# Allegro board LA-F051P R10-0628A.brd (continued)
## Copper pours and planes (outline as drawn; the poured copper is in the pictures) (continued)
SPK_L+_C on BOTTOM (solid shape): 26.65,17.36 26.65,16.6 26.52,16.47 24.49,16.47 23.98,15.96 22.45,15.96 22.2,16.21 22.2,16.85 22.58,17.23 22.96,17.23 23.22,17.48 26.52,17.48
SPK_L-_C on TOP (solid shape): 26.14,20.28 26.14,17.74 25.63,17.23 25.63,15.45 24.49,14.31 22.2,14.31 22.07,14.44 22.07,15.45 22.2,15.58 23.98,15.58 24.49,16.09 24.49,17.48 25.25,18.25 25.25,19.67 25.1,19.67 24.99,19.77 24.99,20.28 25.12,20.41 26.01,20.41
SPK_L-_C on BOTTOM (solid shape): 26.77,15.96 26.77,15.58 26.65,15.45 25.25,15.45 24.61,14.82 24.61,13.93 24.36,13.67 23.47,13.67 23.22,13.93 23.22,14.69 24.74,16.21 26.52,16.21
SPK_OUT_L+ on TOP (solid shape): 27.57,27.02 27.57,25.36 27.53,25.32 27.53,24.99 27.05,24.5 26.83,24.5 26.7,24.62 26.7,24.82 27.33,25.45 27.33,27.02 27.39,27.07 27.52,27.07
SPK_OUT_L+ on TOP (solid shape): 23.35,21.8 23.54,21.74 23.72,21.8 24.61,21.8 24.74,21.68 24.74,20.66 24.61,20.53 24.29,20.53 24.23,20.53 24.23,20.54 23.33,20.54 23.32,20.55 23.28,20.64 23.22,20.72 23.22,21.68 23.34,21.8
SPK_OUT_L+ on IN1 (solid shape): 28.8,25.13 28.8,23.38 27.44,22.01 27.41,22.02 27.01,21.95 26.93,21.55 26.95,21.52 25.71,20.28 24.11,20.28 23.98,20.41 23.98,21.55 24.11,21.68 25.12,21.68 27.15,23.71 27.15,24.39 26.82,24.72 26.82,25 27.07,25.25 27.15,25.31 27.21,25.39 27.23,25.41 28.52,25.41
SPK_OUT_L- on TOP (solid shape): 27.97,27.03 27.97,25.3 28.04,25.23 28.04,25.1 28.42,24.72 28.42,24.22 27.79,23.58 27.79,22.31 27.47,21.99 27.43,22.01 27.01,21.95 26.95,21.52 26.97,21.49 26.02,20.54 25.11,20.54 24.99,20.66 24.99,21.55 26.39,22.95 26.39,23.58 27.66,24.85 27.66,24.97 27.67,24.98 27.71,25.12 27.7,25.27 27.69,25.28 27.69,25.3 27.74,25.35 27.74,27.03 27.79,27.08 27.93,27.08
SPK_OUT_R+ on TOP (solid shape): 28.83,26.99 28.83,26 28.82,25.99 28.82,25.71 28.83,25.68 28.93,25.46 29.15,25.36 29.17,25.36 29.62,24.91 29.66,24.91 29.67,24.9 30.35,24.9 30.59,24.66 30.59,22.77 30.5,22.67 30.5,21.76 30.59,21.66 30.59,21.15 29.37,21.15 29.31,21.21 29.31,23.07 29.57,23.33 29.57,24.52 28.53,25.55 28.53,27 28.61,27.08 28.74,27.08
SPK_OUT_R- on TOP (solid shape): 28.37,27.01 28.37,25.53 29.44,24.47 29.44,23.45 29.06,23.07 29.06,20.66 28.93,20.53 28.17,20.53 28.05,20.65 28.05,21.42 28.04,21.42 28.04,23.58 28.55,24.09 28.55,24.78 28.17,25.16 28.17,25.28 28.14,25.31 28.14,27.01 28.2,27.07 28.31,27.07
SPK_R+_C on TOP (solid shape): 30.69,20.8 30.69,19.98 30.96,19.7 30.96,16.85 30.62,16.51 30.52,16.49 30.45,16.57 29.85,16.77 30.05,16.17 30.13,16.1 30.11,15.99 30.07,15.96 30.07,14.94 29.98,14.8 29.98,14.62 29.98,14.6 29.82,14.44 28.42,14.44 28.17,14.69 28.17,16.34 30.07,18.25 30.07,18.47 30.27,18.75 30.17,19.07 30.07,19.17 30.07,19.26 29.95,19.39 29.95,20.15 29.73,20.37 29.73,20.39 29.72,20.47 29.7,20.54 29.69,20.55 29.69,20.79 29.82,20.91 30.58,20.91
SPK_R+_C on BOTTOM (solid shape): 29.72,14.92 29.72,13.95 29.08,13.32 25.35,13.32 24.99,13.67 24.99,14.13 25.2,14.33 28.19,14.33 28.85,14.99 29.64,14.99
SPK_R-_C on TOP (solid shape): 27.92,21.42 27.92,19.26 27.28,18.63 27.28,18.27 27.28,18.25 27.28,17.74 27.28,17.72 27.28,16.98 27.66,16.6 27.66,14.69 27.41,14.44 26.39,14.44 26.14,14.69 26.14,17.36 26.26,17.48 26.26,17.69 26.26,17.69 26.26,20.08 26.71,20.08 26.71,20.02 26.72,19.97 26.73,19.92 26.76,19.87 26.79,19.83 26.82,19.79 26.86,19.75 26.91,19.73 26.96,19.71 27.01,19.7 27.06,19.69 27.12,19.7 27.17,19.71 27.22,19.73 27.27,19.75 27.31,19.79 27.34,19.83 27.37,19.87 27.4,19.92 27.41,19.97 27.42,20.02 27.42,20.08 27.41,20.13 27.4,20.18 27.37,20.23 27.34,20.27 27.31,20.31 27.27,20.34 27.22,20.37 27.17,20.39 27.12,20.4 27.06,20.41 27.01,20.4 26.96,20.39 26.91,20.37 26.86,20.34 26.82,20.31 26.79,20.27 26.76,20.23 26.73,20.18 26.72,20.13 26.71,20.08 26.26,20.08 26.26,20.33 26.26,20.33 26.26,20.53 27.11,21.38 27.16,21.36 27.21,21.35 27.27,21.34 27.32,21.35 27.37,21.36 27.42,21.38 27.47,21.41 27.51,21.44 27.54,21.48 27.57,21.52 27.58,21.55 27.79,21.55
SPK_R-_C on BOTTOM (solid shape): 27.86,14.92 27.86,14.66 27.71,14.51 25.17,14.51 24.99,14.69 24.99,14.94 25.2,15.15 27.64,15.15
TBT_SVR_IND on TOP (solid shape): 38.9,56.16 38.9,56.14 38.91,56.07 38.94,56.01 38.95,55.99 38.95,55.97 39.05,55.86 39.17,55.86 39.2,55.83 39.2,55.66 39.18,55.59 39.11,55.56 38.91,55.47 38.79,55.28 38.57,55.05 38.57,54.17 38.1,53.71 35.32,53.71 35.14,53.88 35.14,54.21 35.18,54.25 36.49,54.25 36.81,54.57 37.95,54.57 38.2,54.82 38.2,55.27 38.21,55.28 38.21,55.41 38.23,55.42 38.33,55.47 38.39,55.57 38.4,55.59 38.41,55.6 38.41,56.04 38.42,56.08 38.64,56.3 38.76,56.3
TBT_SVR_IND on TOP: 34.77,51.11 34.98,51.32 36.09,51.32 36.22,51.44 36.65,51.44 36.81,51.29 36.81,49.78 36.55,49.53 36.55,48.14 36.22,47.81 35.1,47.81 34.77,48.14
TBT_SVR_IND on IN1: 36.64,49.78 35.43,49.78 35.2,50.01 35.2,54.09 35.8,54.68 37.82,54.68 38.1,54.4 38.1,53.13 36.78,51.81 36.78,49.92
TBT_VBUS on TOP (solid shape): 18.87,56.51 18.87,55.42 19.09,55.2 20.39,55.2 20.8,54.79 20.8,53.43 20.68,53.3 17.88,53.3 17.76,53.43 17.76,54.64 17.76,56.15 18.14,56.54 18.15,56.54 18.21,56.6 18.78,56.6
TBT_VBUS on BOTTOM (solid shape): 20.36,58.37 20.36,54.55 20.22,54.42 18.21,54.42 17.71,54.92 17.71,56.06 18.75,57.1 18.75,58.3 19,58.56 20.17,58.56
TBT_VBUS on BOTTOM: 45.13,76.03 46.2,76.03 46.33,75.9 46.32,75.79 46.33,75.71 46.33,75.58 46.52,75.4 48.49,75.4 48.62,75.27 48.62,74.96 48.62,74.43 48.51,74.33 48.24,74.33 47.78,73.87 45.65,73.87 44.69,74.83 44.68,74.83 44.1,75.41 44.1,75.88 44.25,76.03
TBT_VBUS on VCC: 8.84,54.44 5.35,57.94 5.71,58.04 5.87,58.39 5.87,59.19 5.56,59.62 5.06,59.47 5.06,62.11 5.56,61.96 5.86,62.39 5.86,63.19 5.56,63.62 5.06,63.46 5.06,66.64 7.12,67.56 8.1,68.4 8.47,69.64 8.47,70.12 8.98,71.34 10.2,71.85 14.5,71.85 16.11,72.51 16.77,74.12 16.77,79.23 44,79.23 45.15,79.66 45.75,80.73 47.73,80.73 47.73,70.68 44.7,67.65 39.6,67.65 37.57,69.68 31.11,69.68 30.76,69.33 30.76,67.65 24,67.65 21.57,65.21 21.57,55.44 20.57,54.44 ; 4 cut-outs
TBT_VBUS_L on TOP (solid shape): 22.26,59.92 22.26,59.91 22.33,59.79 22.44,59.73 22.45,59.72 22.59,59.59 22.59,59.38 22.28,59.06 22.27,59.06 22.21,59.03 22.18,59 21.82,58.64 21.82,58.63 21.33,58.15 21.18,58.15 21.16,58.13 20.86,58.13 20.79,58.06 20.77,58.06 20.77,58.04 20.73,58 20.73,55.63 20.55,55.46 19.16,55.46 19.09,55.53 19.09,56.4 19.53,56.84 19.53,57.73 20.54,58.74 20.62,58.74 20.63,58.75 20.94,58.8 21.1,59.07 21.1,59.09 21.26,59.25 21.26,59.33 21.29,59.36 21.29,59.45 21.51,59.67 21.69,59.67 21.87,59.85 21.87,60.03 21.95,60.11 22.07,60.11
N52893865 on TOP (solid shape): 174.1,19.47 174.1,18.52 174.47,18.14 174.47,17.61 174.22,17.36 174.04,17.36 173.97,17.39 173.94,17.46 173.79,17.78 173.43,17.81 173.4,17.79 173.2,17.99 172.06,17.99 172,18.06 172,18.7 172.17,18.88 172.7,18.88 173.36,19.54 174.02,19.54
N52893895 on TOP (solid shape): 170.6,18.86 170.6,18.06 170.54,17.99 169.77,17.99 169.65,18.12 168.5,18.12 168.38,18.23 168.38,18.86 168.53,19.01 170.46,19.01
N52922903 on TOP (solid shape): 178.98,31.77 178.98,30.73 178.51,30.26 178.51,29.79 178.23,29.5 178.23,28.66 177.27,28.66 177.14,28.79 177.14,30.99 177.68,31.53 177.93,31.53 178.24,31.84 178.92,31.84
N52922958 on TOP (solid shape): 181.08,31.81 181.08,30.39 181.26,30.2 181.42,30.2 181.53,30.18 181.64,30.2 182.04,30.2 182.04,30.2 182.08,30.16 182.08,29.4 182.03,29.35 180.52,29.35 180.37,29.5 180.37,31.81 180.44,31.89 181,31.89
N52925836 on TOP (solid shape): 50.27,21.57 50.27,20.91 50.19,20.84 48.79,20.84 48.59,21.04 48.3,21.04 48.22,21.12 48.22,22.11 48.23,22.11 48.23,22.3 48.26,22.34 49.5,22.34
N52925896 on TOP (solid shape): 50.29,19.36 50.29,18.75 50.14,18.6 50.14,18.41 50.07,18.36 50.02,18.3 49.96,18.26 49.89,18.28 49.36,17.91 49.97,17.73 50.04,17.76 50.12,17.73 50.14,17.71 50.14,17.23 49.51,16.6 48.79,16.6 47.93,17.46 47.93,19.03 48.08,19.19 48.7,19.19 49.04,19.52 50.14,19.52
N52930519 on TOP (solid shape): 40.36,44.15 40.36,42.25 40.23,42.12 39.22,42.12 38.31,43.03 38.31,43.07 38.27,43.07 38.2,43.14 37.69,43.14 37.57,43.27 37.57,43.9 37.69,44.03 38.58,44.03 38.84,44.28 40.23,44.28
N52930575 on TOP (solid shape): 36.42,45.42 36.42,44.66 36.25,44.48 36.25,43.21 36.17,43.14 35.41,43.14 35.15,43.39 35.15,44.1 35.15,44.15 35.16,44.16 35.18,44.28 35.16,44.39 35.15,44.4 35.15,44.46 34.9,44.72 34.9,45.42 35.03,45.55 36.3,45.55
N52934489 on TOP (solid shape): 28.74,41.99 28.95,41.92 29.17,42 29.44,42 30.01,41.42 30.18,41.42 30.23,41.41 30.28,41.41 31.37,41.41 31.37,41.42 31.6,41.42 31.79,41.23 32.36,41.23 32.49,41.11 32.49,40.6 32.36,40.47 30.25,40.47 30.23,40.5 30.23,40.55 29.97,40.8 29.95,40.83 28.52,40.83 28.42,40.93 28.42,41.74 28.68,42 28.72,42
N52934545 on TOP (solid shape): 34.77,41.11 34.77,39.2 34.65,39.07 33.88,39.07 33.76,39.2 33.76,41.11 33.88,41.23 34.65,41.23
N56704068 on BOTTOM (solid shape): 35.15,77.56 34.65,77.05 34.65,76.54 34.52,76.41 34.27,76.41 33.88,76.79 33.88,79.08 34.01,79.21 35.15,79.21
N56715138 on BOTTOM (solid shape): 50.78,80.69 50.78,78.45 50.69,78.36 48.57,78.36 48.49,78.44 48.11,78.44 47.98,78.57 47.98,80.35 48.4,80.77 50.7,80.77
N56728350 on BOTTOM (solid shape): 55.79,55.14 55.79,54.82 55.54,54.57 55.54,53.81 55.41,53.68 55.11,53.68 54.84,53.4 54.84,53.35 54.84,52.03 54.65,51.83 54.63,51.83 54.57,51.81 54.52,51.77 54.36,51.77 54.35,51.81 53.89,52.06 53.67,51.59 53.68,51.53 53.7,51.46 53.7,51.28 53.53,51.11 52.86,51.11 52.67,51.3 52.67,52.6 53.54,53.47 53.54,54.79 53.95,55.2 55.73,55.2
N57177583 on TOP (solid shape): 154.79,75.78 154.79,74.3 154.66,74.18 153.9,74.18 153.44,74.63 152.98,74.63 152.93,74.68 152.93,75.68 153.02,75.76 153.86,75.76 154.06,75.78 154.22,75.9 154.66,75.9
N57177931 on TOP (solid shape): 162.41,48.09 162.41,46.82 162.28,46.69 161.9,46.69 161.65,46.95 160.63,46.95 160.5,47.08 160.5,48.09 160.56,48.14 161.57,48.14 161.72,48.29 162.2,48.29
N57178338 on TOP (solid shape): 163.8,67.14 163.8,65.56 163.81,65.38 163.67,65.26 163.62,65.09 163.62,65.07 163.59,65.05 163.59,64.9 163.55,64.86 161.77,64.86 161.65,64.98 161.65,65.2 162.02,65.2 162.03,65.19 162.54,65.52 162.03,65.84 162.02,65.83 161.82,65.83 161.75,65.91 161.75,66.81 161.82,66.89 162.79,66.89 163.17,67.27 163.68,67.27
N57965459 on BOTTOM: 54.19,60.05 54.74,60.05 54.74,60.03 54.76,60.05 56.02,60.05 56.11,59.97 56.11,58.94 55.98,58.67 56.11,58.4 56.11,57.55 56.49,57.17 56.49,55.65 56.3,55.46 54.23,55.46 54.1,55.59 54.1,55.6 54.1,59.96
N62098363 on TOP (solid shape): 202.41,41.23 202.41,37.65 202.36,37.6 200.36,37.6 200.33,37.63 200.33,39 200.84,39.51 200.84,41.18 200.97,41.31 202.34,41.31
N65247919 on TOP (solid shape): 37.1,36.31 37.38,36.31 37.45,36.23 37.45,35.77 37.28,35.59 36.67,35.59 36.51,35.44 36.51,34.75 36.48,34.72 36.4,34.6 36.37,34.46 36.34,34.39 36.27,34.36 35.85,34.36 35.75,34.46 35.75,36.36 36.03,36.64 36.77,36.64
N119009632 on BOTTOM (solid shape): 31.46,75.4 31.85,75.4 31.98,75.27 31.98,74.77 31.97,74.77 31.97,74.65 31.85,74.53 31.37,74.53 31.36,74.5 31.14,74.5 31.14,74.5 30.68,74.5 30.66,74.53 30.34,74.74 30.02,74.54 30.01,74.51 29.31,74.51 28.93,74.89 28.93,75.85 29.19,76.11 30.75,76.11

Small or netless copper shapes (teardrops, artwork), in the pictures only: 19 on TOP, 20 on BOTTOM, 5 on IN2, 1 on IN3, 1 on IN4

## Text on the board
Ref Des/Silkscreen Bottom: RTC | Battery | DC-IN | Speaker | WLAN+BT | Board | Keyboard | Camera | Touch | Screen | Fan | Touch Pad | LCD | IO Board | UART | H11 | H14 | H16 | H15 | H10 | H6 | H17
User.Comments: LA-F051P | 2017-06-28 | 2018-06-28 | CAZ70 | Monika
Ref Des/Silkscreen Top: S1
BODY_CENTER: LAYER | NAME | L3 | L1 | L2 | L5 | L4 | L6 | L7 | L8 | L9 | L10 | LA-F051P | GND2 | VCC | TOP | GND1 | IN2 | IN3 | IN4 | IN1 | GND3 | BOT | LS-XXXXP
User.38: Impedence
User.39: FIGURE | SIZE | 8.0 | 10.0 | 16.0 | 26.0 | 31.0 | 79.0 | 130.0 | 30.0 | 40.0 | 43.0 | 63.0 | 71.0 | 51.0x31.0 | 55.0x24.0 | 63.0x24.0 | 75.0x31.0 | 126.0x31.0 | 37.0x30.0 | 91.0x71.0 | DRILL CHART: TOP to BOTTOM | ALL UNITS ARE IN MILS | TOLERANCE | +3.0/-3.0 | +2.0/-2.0 | PLATED | NON-PLATED | QTY | 4976 | 54 | 12 | 2 | 9 | 8 | 7 | 1 | 4
User.40: trace Width | 4.6 | 3.2 | 3.5 | 5 | Width/Space | 4.5/3.5 | 3.6/4 | 4/4.8 | 5/5 | 4 | 4/4.4 | L4/L6 | 6.4/3.5 | L3 | L8 | L9-GND3 | L4-GND2 | L10-BOT | L6-IN3 | L3-IN1 | L5-IN2 | L7-VCC | L2-GND1 | MP_HR_1_0mm-10L-stack-up-151125.pdf | L1-TOP | L8-IN4 | LAYER | NAME | STACKUP: 10 LAYER | 40 ohm | 50 ohm | 75 ohm | THICKNESS=1.0mm | 85 ohm | ref | 90 ohm
